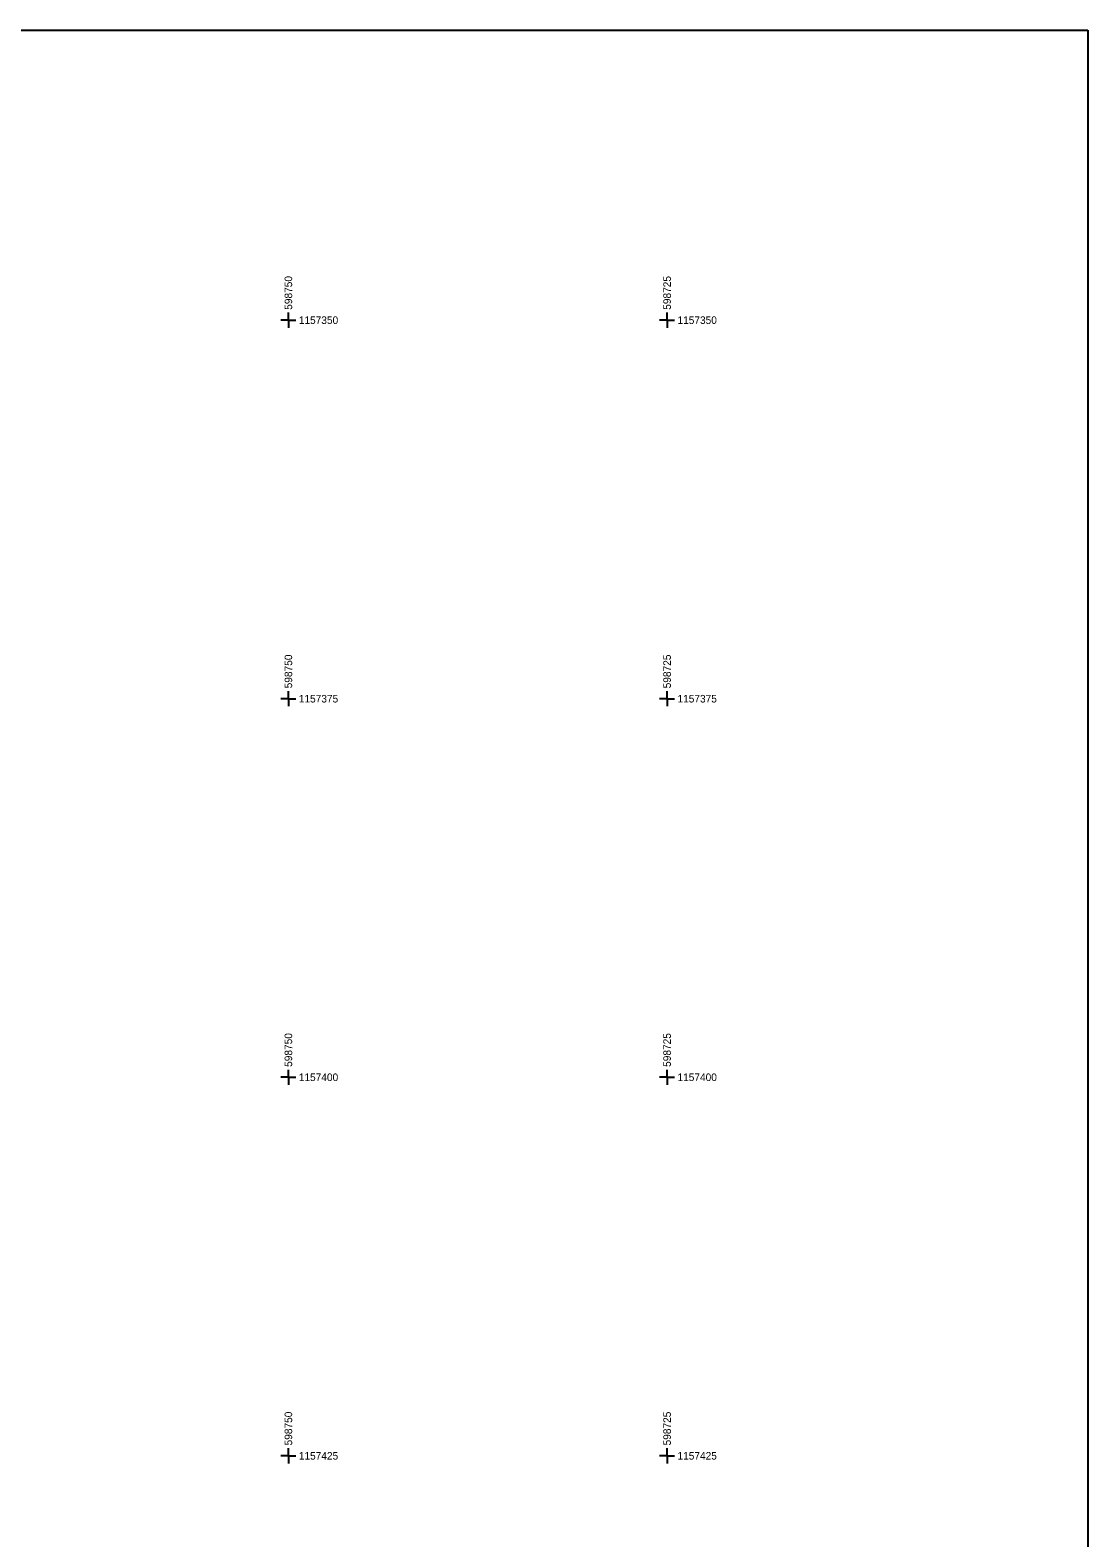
# Model space of a CAD drawing. Extents: x -598845 to -598697, y -1157541 to -1157331.
# Drawn here: x -598767 to -598697.2, y -1157430.4 to -1157330.8 of the extents above; entities that cross this region are included whole.
import ezdxf

# ---------------------------------------------------------------- set-up
doc = ezdxf.new("R2010")
doc.units = 0
for name, color, linetype in [('Vrstva 1', 7, 'Continuous'), ('Vrstva 52', 7, 'Continuous'), ('Vrstva 62', 7, 'Continuous')]:
    doc.layers.add(name, color=color, linetype=linetype)

msp = doc.modelspace()

# ---------------------------------------------------------------- linework, layer by layer
at = {"layer": 'Vrstva 1'}
for p, q in [((-598845.222, -1157330.847), (-598697.222, -1157330.847)), ((-598697.222, -1157330.847), (-598697.223, -1157540.847))]:
    msp.add_line(p, q, dxfattribs=at)
at = {"layer": 'Vrstva 62'}
for p, q in [((-598750, -1157350), (-598750, -1157349.5)), ((-598725, -1157350), (-598725, -1157349.5)), ((-598750, -1157350), (-598750.5, -1157350)), ((-598750, -1157350), (-598749.5, -1157350)), ((-598750, -1157350), (-598750, -1157350.5)), ((-598725, -1157350), (-598725.5, -1157350)), ((-598725, -1157350), (-598724.5, -1157350)), ((-598725, -1157350), (-598725, -1157350.5)), ((-598750, -1157375), (-598750, -1157374.5)), ((-598725, -1157375), (-598725, -1157374.5)), ((-598750, -1157375), (-598750.5, -1157375)), ((-598750, -1157375), (-598749.5, -1157375)), ((-598750, -1157375), (-598750, -1157375.5)), ((-598725, -1157375), (-598725.5, -1157375)), ((-598725, -1157375), (-598724.5, -1157375)), ((-598725, -1157375), (-598725, -1157375.5)), ((-598750, -1157400), (-598750.5, -1157400)), ((-598750, -1157400), (-598750, -1157399.5)), ((-598750, -1157400), (-598749.5, -1157400)), ((-598750, -1157400), (-598750, -1157400.5)), ((-598725, -1157400), (-598725.5, -1157400)), ((-598725, -1157400), (-598725, -1157399.5)), ((-598725, -1157400), (-598724.5, -1157400)), ((-598725, -1157400), (-598725, -1157400.5)), ((-598750, -1157425), (-598750.5, -1157425)), ((-598750, -1157425), (-598750, -1157424.5)), ((-598750, -1157425), (-598749.5, -1157425)), ((-598750, -1157425), (-598750, -1157425.5)), ((-598725, -1157425), (-598725.5, -1157425)), ((-598725, -1157425), (-598725, -1157424.5)), ((-598725, -1157425), (-598724.5, -1157425)), ((-598725, -1157425), (-598725, -1157425.5))]:
    msp.add_line(p, q, dxfattribs=at)

# ---------------------------------------------------------------- texts
at = {"layer": 'Vrstva 52'}
for s, p in [(' 598750', (-598749.75, -1157349.5)), (' 598725', (-598724.75, -1157349.5)), (' 598750', (-598749.75, -1157374.5)), (' 598725', (-598724.75, -1157374.5)), (' 598750', (-598749.75, -1157399.5)), (' 598725', (-598724.75, -1157399.5)), (' 598750', (-598749.75, -1157424.5)), (' 598725', (-598724.75, -1157424.5))]:
    msp.add_text(s, height=0.5, rotation=90, dxfattribs=at).set_placement(p)
for s, p in [(' 1157350', (-598749.5, -1157350.25)), (' 1157350', (-598724.5, -1157350.25)), (' 1157375', (-598749.5, -1157375.25)), (' 1157375', (-598724.5, -1157375.25)), (' 1157400', (-598749.5, -1157400.25)), (' 1157400', (-598724.5, -1157400.25)), (' 1157425', (-598749.5, -1157425.25)), (' 1157425', (-598724.5, -1157425.25))]:
    msp.add_text(s, height=0.5, dxfattribs=at).set_placement(p)

doc.saveas('drawing.dxf')
